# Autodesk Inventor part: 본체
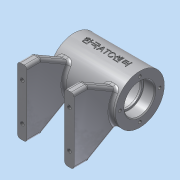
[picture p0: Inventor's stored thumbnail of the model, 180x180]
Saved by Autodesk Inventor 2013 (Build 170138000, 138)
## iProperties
Created: 2018-05
Part Number: 본체
Material: 알루미늄 6061
Document SubType Name: Modeling
Designer: dgall
Density: 2.71 g/cm^3
Mass: 318.856 g
Surface Area: 375.823 cm^2
Volume: 117.659 cm^3
Author: dgall
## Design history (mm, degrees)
sketch "스케치1"
  geometry: L1 (-35, 0)-(35, 0); L2 (-35, 26)-(-35, 16); L3 (-35, 16)-(-23, 16); L4 (-23, 16)-(-23, 14); L5 (-23, 14)-(-21, 14); L6 (-21, 14)-(-21, 21); L7 (-21, 21)-(21, 21); L8 (21, 21)-(21, 14); L9 (21, 14)-(23, 14); L10 (23, 14)-(23, 16); L11 (23, 16)-(35, 16); L12 (35, 16)-(35, 26); L13 (35, 26)-(-35, 26); 2 further points
  constraints: 26 end point, 5 vertical, 4 horizontal, 2 horizontal alignment, 2 vertical alignment, 1 coincident, 1 midpoint
  dimensions: "d15" = 42 distance of L6.end L7.end; "d17" = 70 distance of L1.start L1.end; "d18" = 12 distance of L2.end L3.end; "d19" = 2 distance of L4.end L5.end; "d20" = 2 distance of L8.end L9.end; "d21" = 12 distance of L10.end L11.end; "d22" = 32 diameter of L3 L1; "d23" = 28 diameter of L5 L1; "d24" = 52 diameter of L13 L1; "d25" = 42 diameter of L7 L1
revolve "회전1" sketch "스케치1" stored, may be unused: angle "d26" = 90 deg
node "작업 평면1"
sketch "스케치2"
  geometry: L1 (-5, 23.029)-(-5, 29); L2 (-5, 29)-(0, 29); L3 (0, 23.029)-(-5, 23.029); L4 (0, 29)-(0, 0); C1 r 26 at (0, 0) reference; C2 r 21 at (0, 0) reference; 1 further point
  constraints: 8 end point, 2 horizontal, 2 vertical, 1 point on line
  dimensions: "d27" = 10 diameter of L1 L4; "d29" = 29 distance of L2.end point (0, 0); "d30" = 23.02906 distance from line of point (0, 0) L3
revolve "회전2" sketch "스케치2" stored, may be unused: angle "d31" = 90 deg
sketch "스케치3"
  geometry: L1 (0, 0)-(17.538, -48.184); L2 (0, 0)-(0, -46.16); L3 (13.163, -18.621)-(15.557, -25.199); L4 (15.557, -25.199)-(9.919, -27.251); L5 (13.163, -18.621)-(7.524, -20.673)
  constraints: 10 end point, 2 perpendicular, 2 point on line, 1 parallel, 1 vertical
  dimensions: "d32" = 20 deg angle of L2 L1; "d33" = 12 diameter of L3 L1; "d35" = 29 distance from line of L1.start L4; "d36" = 22 distance from line of L1.start L5
revolve "회전3" sketch "스케치3" stored, may be unused: angle "d37" = 90 deg
sketch "스케치4"
  geometry: C1 r 5 at (0, 0) reference; 1 further point
  constraints: 1 coincident
hole "구멍1" sketch "스케치4" at (0, 0) diameter "d38" = 5.188; stored, may be unused: countersink angle "d42" = 90 deg, drill point angle "d44" = 118 deg; dims "d39" = 6, "d40" = 4, "d41" = 2, "d43" = 20
node "작업 평면2"
sketch "스케치5"
  geometry: 1 further point
node "작업 평면3"
sketch "스케치6"
  geometry: L1 (-35, -65)-(35, -65); L2 (-35, -65)-(-35, -50); L3 (-35, -50)-(-16.278, -17.573); L4 (-16.278, -17.573)-(0, -24); L5 (0, -24)-(16.278, -17.573); L6 (16.278, -17.573)-(35, -50); L7 (35, -50)-(35, -65); C1 r 26 at (0, 0) reference; C2 r 21 at (0, 0) reference; 2 further points
  constraints: 14 end point, 2 horizontal alignment, 2 vertical alignment, 1 horizontal, 1 midpoint, 1 vertical
  dimensions: "d47" = 70 distance of L1.start L1.end; "d49" = 65 distance from line of point (0, 0) L1; "d50" = 15 distance of L6.end L1.end; "d51" = 15 distance of L1.start L2.end; "d52" = 30 deg angle of L2 L3; "d54" = 30 deg angle of L6 L7; "d55" = 6.42684 vertical distance of L4.end L5.end; "d56" = 16.27835 horizontal distance of L4.end L5.end
extrude "돌출1" join sketch "스케치6" distance "d57" = 10; taper "d58" = 0 deg
sketch "스케치7"
  geometry: C1 r 26 at (0, 0) reference; 3 further points
  constraints: 3 vertical alignment, 1 coincident, 3 other
hole "구멍2" sketch "스케치7" at (0, 21) diameter "d59" = 3.242; stored, may be unused: countersink angle "d63" = 90 deg, drill point angle "d65" = 118 deg; dims "d60" = 8, "d61" = 4, "d62" = 2, "d64" = 10
fillet "모깎기1" dims "d69" = 0.3
fillet "모깎기2" dims "d70" = 2
fillet "모깎기3" dims "d71" = 3
fillet "모깎기4" dims "d72" = 3
fillet "모깎기5" dims "d73" = 3
fillet "모깎기6" dims "d74" = 3
chamfer "모따기1" distance "d75" = 1; stored, may be unused: second distance "d76" = 2, angle "d77" = 45 deg
sketch "스케치8"
  geometry: L1 (3, 67)-(7, 67) reference; C1 r 4 at (5, 52); 3 further points
  constraints: 1 centre point, 1 coincident, 1 midpoint, 1 vertical alignment
  dimensions: "d78" = 20 vertical distance of point (-20, 32) C1.centre
hole "구멍3" sketch "스케치8" at (5, 52) diameter "d79" = 4.134; stored, may be unused: countersink angle "d83" = 90 deg, drill point angle "d85" = 118 deg; dims "d80" = 8, "d81" = 4, "d82" = 2, "d84" = 10
node "작업 평면4"
node "작업 평면5"
sketch "스케치9"
  geometry: L1 (-35, -26)-(-35, 26) reference; L2 (-35, 26)-(35, 26) reference; 2 further points
  constraints: 1 other
  dimensions: "d87" = 35 distance from line of L1 point (0, 0); "d88" = 26 distance from line of L2 point (0, 0)
feature "엠보싱1" sketch "스케치9" dims "d89" = 0.5, "d90" = 0
sketch "스케치10"
  geometry: C1 r 6 at (0, 0) reference; 1 further point
  constraints: 1 coincident
hole "구멍4" sketch "스케치10" at (0, 0) diameter "d91" = 5.188; stored, may be unused: countersink angle "d95" = 90 deg, drill point angle "d97" = 118 deg; dims "d92" = 8, "d93" = 4, "d94" = 2, "d96" = 20
node "솔리드1"
mirror "대칭1"
pattern_circular "원형 패턴1" dims angle "d67" = 360 deg
mirror "대칭2"
mirror "대칭3"
mirror "대칭4"
node "절단 모서리 투영1"
node "절단 모서리 투영2"
other parameters: "d45" = -65, "d86" = 55
